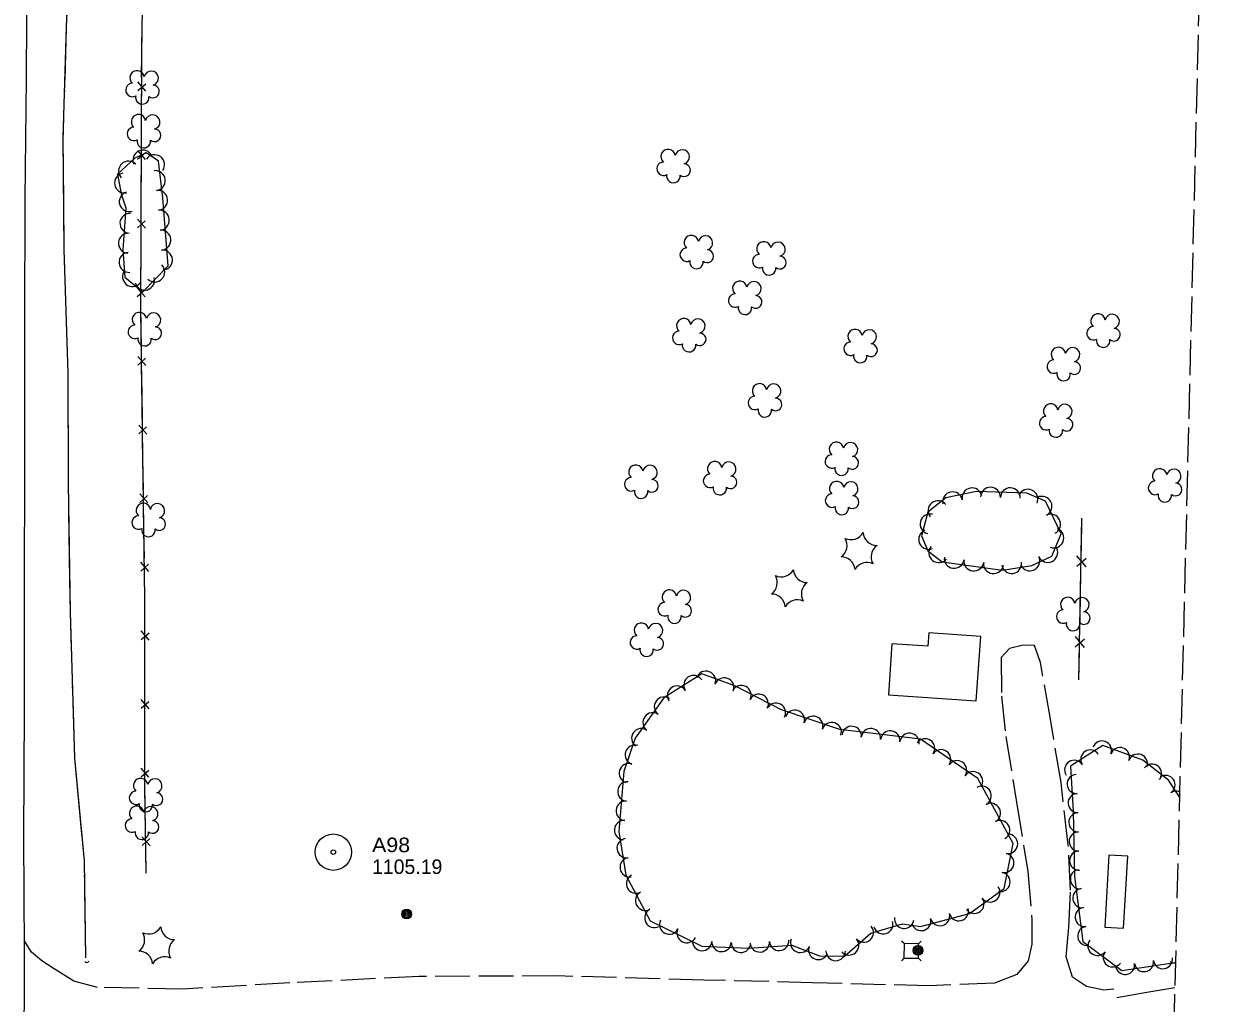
# Model space of a CAD drawing. Extents: x 296583 to 298831, y 44522 to 45957.
# Drawn here: x 297700.4 to 298192.3, y 45106.2 to 45510.3 of the extents above; entities that cross this region are included whole.
import ezdxf

# ---------------------------------------------------------------- set-up
doc = ezdxf.new("R2010")
doc.units = 0
doc.header["$LTSCALE"] = 2.4
doc.linetypes.add('LONG_DASHED', pattern=[7.5, 6, -1.5])
for name, color, linetype, lineweight in [('11', 7, 'Continuous', 25), ('12', 7, 'Continuous', 25), ('14', 7, 'Continuous', 13), ('15', 7, 'Continuous', 13), ('17', 7, 'LONG_DASHED', 13), ('18', 7, 'Continuous', 13), ('19', 7, 'Continuous', 13), ('21', 7, 'Continuous', 25), ('4', 7, 'Continuous', 13), ('6', 7, 'Continuous', 13)]:
    doc.layers.add(name, color=color, linetype=linetype, lineweight=lineweight)

msp = doc.modelspace()

# ---------------------------------------------------------------- linework, layer by layer
at = {"layer": '11'}
msp.add_lwpolyline([(297700.604, 45078.854), (297700.618, 45127.759), (297700.405, 45174.635), (297700.7, 45227.338), (297700.641, 45277.618), (297700.756, 45327.982), (297700.817, 45386.673), (297700.954, 45438.105), (297701.512, 45487.567), (297701.749, 45536.979), (297702.068, 45585.788), (297702.731, 45637.819), (297704.078, 45687.047), (297705.432, 45724.307), (297707.239, 45766.902), (297708.944, 45803.473), (297710.461, 45829.675)], dxfattribs=at)
at = {"layer": '12'}
for points in [[(298093.641, 45230.913), (298095.475, 45257.543), (298073.997, 45259.022), (298073.613, 45253.456), (298058.846, 45254.473), (298057.396, 45233.409)], [(298154.497, 45137.077), (298156.22, 45166.826), (298148.396, 45167.279), (298146.673, 45137.53)]]:
    msp.add_lwpolyline(points, close=True, dxfattribs=at)
at = {"layer": '14'}
for centre, radius in [((297858.511, 45142.941), 2.018), ((297858.498, 45142.938), 1.518), ((297858.538, 45142.944), 1.008), ((297858.528, 45142.948), 0.502), ((298069.604, 45127.957), 2.018), ((298069.591, 45127.954), 1.518), ((298069.631, 45127.96), 1.008), ((298069.621, 45127.964), 0.502)]:
    msp.add_circle(centre, radius, dxfattribs=at)
at = {"layer": '15'}
for p, q in [((297749.101, 45499.627), (297749.256, 45509.749)), ((297747.498, 45482.782), (297750.732, 45485.614)), ((297750.791, 45482.598), (297747.511, 45486.388)), ((297748.984, 45471.301), (297749.019, 45481.425)), ((297748.944, 45459.791), (297748.984, 45471.301)), ((297747.4, 45454.456), (297750.634, 45457.288)), ((297750.693, 45454.272), (297747.413, 45458.063)), ((297748.885, 45442.975), (297748.921, 45453.099)), ((297748.846, 45431.465), (297748.885, 45442.975)), ((297747.302, 45426.131), (297750.536, 45428.962)), ((297750.594, 45425.947), (297747.314, 45429.737)), ((297748.787, 45414.65), (297748.822, 45424.773)), ((297748.747, 45403.14), (297748.787, 45414.65)), ((297747.204, 45397.805), (297750.438, 45400.637)), ((297750.496, 45397.621), (297747.216, 45401.411)), ((297748.957, 45374.816), (297748.792, 45386.325)), ((297750.804, 45369.329), (297747.457, 45373.061)), ((297747.508, 45369.455), (297750.691, 45372.343)), ((297749.198, 45358.002), (297749.053, 45368.124)), ((297749.363, 45346.493), (297749.198, 45358.002)), ((297751.21, 45341.006), (297747.863, 45344.738)), ((297747.914, 45341.132), (297751.097, 45344.02)), ((297749.604, 45329.679), (297749.459, 45339.801)), ((297749.769, 45318.17), (297749.604, 45329.679)), ((297751.616, 45312.683), (297748.269, 45316.415)), ((297748.321, 45312.809), (297751.504, 45315.697)), ((297750.01, 45301.356), (297749.865, 45311.479)), ((298136.056, 45239.621), (298137.275, 45306.365)), ((298137.027, 45292.804), (298137.275, 45306.365)), ((297750.175, 45289.847), (297750.01, 45301.356)), ((297752.022, 45284.36), (297748.675, 45288.092)), ((298135.116, 45286.546), (298138.975, 45289.826)), ((298138.992, 45286.271), (298135.193, 45290.795)), ((297748.727, 45284.486), (297751.91, 45287.375)), ((297750.416, 45273.033), (297750.271, 45283.156)), ((298136.666, 45272.993), (298136.883, 45284.92)), ((298136.418, 45259.432), (298136.666, 45272.993)), ((297748.869, 45256.185), (297752.097, 45259.024)), ((297752.162, 45256.008), (297748.874, 45259.792)), ((297750.379, 45244.707), (297750.393, 45254.831)), ((298134.506, 45253.174), (298138.366, 45256.454)), ((298138.382, 45252.899), (298134.584, 45257.423)), ((298136.056, 45239.621), (298136.274, 45251.548)), ((297750.363, 45233.197), (297750.379, 45244.707)), ((297748.831, 45227.859), (297752.059, 45230.698)), ((297752.124, 45227.682), (297748.836, 45231.466)), ((297750.341, 45216.382), (297750.354, 45226.505)), ((297750.325, 45204.871), (297750.341, 45216.382)), ((297748.793, 45199.534), (297752.021, 45202.372)), ((297752.086, 45199.356), (297748.798, 45203.14)), ((297750.648, 45176.549), (297750.438, 45188.057)), ((297752.516, 45171.069), (297749.154, 45174.788)), ((297749.22, 45171.182), (297752.392, 45174.083)), ((297750.954, 45159.736), (297750.77, 45169.858))]:
    msp.add_line(p, q, dxfattribs=at)
for points in [[(297750.954, 45159.736), (297750.312, 45194.971), (297750.417, 45272.978), (297748.709, 45392.083), (297749.076, 45497.953), (297750.665, 45602.374), (297754.315, 45709.699), (297757.299, 45776.061), (297759.438, 45839.359)], [(297749.042, 45488.117), (297749.076, 45497.953), (297749.101, 45499.627)], [(297748.792, 45386.325), (297748.709, 45392.083), (297748.724, 45396.448)], [(297750.402, 45261.523), (297750.417, 45272.978), (297750.416, 45273.033)], [(297750.438, 45188.057), (297750.312, 45194.971), (297750.316, 45198.179)]]:
    msp.add_lwpolyline(points, dxfattribs=at)
msp.add_arc((297726.382, 45124.066), 1.068, 217.51639, 323.75596, dxfattribs=at)
at = {"layer": '17'}
for points in [[(298150.422, 45111.928), (298146.293, 45111.523), (298139.171, 45113.083), (298133.366, 45116.913), (298130.79, 45125.314), (298131.91, 45137.522), (298132.54, 45152.831), (298131.641, 45171.346), (298128.674, 45197.228), (298124.272, 45223.339), (298120.181, 45246.762), (298117.621, 45253.745), (298113.041, 45253.963), (298107.373, 45252.469), (298103.951, 45248.761), (298104.086, 45232.906), (298105.855, 45216.199), (298110.309, 45189.111), (298114.899, 45160.471), (298116.651, 45140.372), (298116.652, 45130.449), (298115.051, 45123.584), (298110.394, 45117.953), (298101.195, 45114.428), (298074.198, 45113.28), (298026.037, 45114.598), (297981.096, 45115.677), (297920.614, 45117.389), (297863.611, 45117.162), (297810.275, 45114.518), (297766.019, 45111.98), (297730.888, 45112.634), (297721.051, 45115.297), (297712.957, 45120.288), (297707.796, 45123.568), (297703.637, 45127.194), (297700.599, 45132.01)], [(298151.682, 45108.52), (298164.075, 45110.74), (298175.618, 45112.686)]]:
    msp.add_lwpolyline(points, dxfattribs=at)
at = {"layer": '18'}
for points in [[(297739.149, 45448.318), (297740.617, 45440.211), (297742.502, 45434.351), (297741.26, 45417.106), (297742.138, 45405.773), (297749.583, 45399.778), (297759.991, 45410.477), (297757.731, 45438.5), (297755.941, 45453.686), (297751.042, 45457.155), (297746.201, 45454.912)], [(298104.537, 45284.828), (298116.614, 45286.711), (298124.9, 45290.602), (298128.707, 45299.852), (298122.181, 45313.301), (298114.549, 45316.691), (298093.801, 45317.294), (298081.064, 45314.666), (298073.6, 45308.805), (298071.019, 45298.976), (298073.7, 45292.847), (298079.536, 45288.224)], [(298090.837, 45143.154), (298105.215, 45153.446), (298108.897, 45172.021), (298094.318, 45198.905), (298070.605, 45215.121), (298037.286, 45219.121), (298013.251, 45227.181), (297993.956, 45237.063), (297980.298, 45242.069), (297964.705, 45232.099), (297952.75, 45215.512), (297948.188, 45201.706), (297946.097, 45176.958), (297948.958, 45158.947), (297959.036, 45140.097), (297980.271, 45129.706), (297999.867, 45128.812), (298017.508, 45130.154), (298028.902, 45125.679), (298039.226, 45125.563), (298050.134, 45135.038), (298063.173, 45138.949), (298070.629, 45137.835)]]:
    msp.add_lwpolyline(points, close=True, dxfattribs=at)
msp.add_lwpolyline([(298177.543, 45191.331), (298172.95, 45198.187), (298162.451, 45206.457), (298145.877, 45212.524), (298132.607, 45203.963), (298133.619, 45185.431), (298134.192, 45158.472), (298137.653, 45131.66), (298153.812, 45119.639), (298175.82, 45122.997), (298175.873, 45123.078)], dxfattribs=at)
for centre, radius, start, end in [((297747.165, 45488.034), 2.974, 7.98733, 229.22121), ((297753.017, 45487.878), 2.975, 285.63814, 168.61141), ((297745.269, 45483.006), 2.777, 90.95822, 298.73121), ((297753.74, 45482.404), 2.611, 230.34337, 88.27598), ((297749.322, 45479.975), 2.783, 167.63523, 8.64628), ((297747.756, 45469.939), 2.974, 7.98733, 229.22121), ((297753.608, 45469.783), 2.975, 285.63814, 168.61141), ((297745.86, 45464.911), 2.777, 90.95822, 298.73121), ((297754.331, 45464.309), 2.611, 230.34337, 88.27598), ((297749.913, 45461.88), 2.783, 167.63523, 8.64628), ((297749.571, 45454.095), 4.123, 24.86756, 204.85223), ((297754.385, 45452.144), 4.123, 324.70521, 144.68989), ((297966.431, 45455.552), 2.974, 7.98733, 229.22121), ((297972.283, 45455.396), 2.975, 285.63814, 168.61141), ((297743.634, 45449.557), 4.123, 43.08537, 223.07004), ((297754.719, 45445.62), 4.123, 276.73019, 96.71487), ((297964.535, 45450.524), 2.777, 90.95822, 298.73121), ((297973.006, 45449.922), 2.611, 230.34337, 88.27598), ((297742.007, 45444.645), 4.123, 100.27146, 280.25613), ((297968.588, 45447.493), 2.783, 167.63523, 8.64628), ((297743.936, 45436.94), 4.123, 107.83921, 287.82389), ((297755.646, 45437.507), 4.123, 274.61847, 94.60315), ((297744.208, 45427.991), 4.123, 85.88828, 265.87296), ((297756.309, 45429.288), 4.123, 274.61847, 94.60315), ((297756.972, 45421.069), 4.123, 274.61847, 94.60315), ((297743.615, 45419.767), 4.123, 85.88828, 265.87296), ((297975.992, 45420.052), 2.974, 7.98733, 229.22121), ((297981.844, 45419.896), 2.975, 285.63814, 168.61141), ((298005.955, 45417.43), 2.974, 7.98733, 229.22121), ((298011.807, 45417.274), 2.975, 285.63814, 168.61141), ((297743.831, 45411.866), 4.123, 94.43768, 274.42236), ((297757.634, 45412.85), 4.123, 274.61847, 94.60315), ((297974.096, 45415.024), 2.777, 90.95822, 298.73121), ((297982.567, 45414.422), 2.611, 230.34337, 88.27598), ((297754.475, 45407.902), 4.123, 225.79754, 45.78222), ((297978.149, 45411.993), 2.783, 167.63523, 8.64628), ((298004.059, 45412.402), 2.777, 90.95822, 298.73121), ((298012.53, 45411.8), 2.611, 230.34337, 88.27598), ((297745.284, 45406.01), 4.123, 141.16531, 321.14999), ((297750.309, 45404.581), 4.123, 195.79754, 15.78222), ((298008.112, 45409.371), 2.783, 167.63523, 8.64628), ((297995.994, 45401.167), 2.974, 7.98733, 229.22121), ((298001.846, 45401.011), 2.975, 285.63814, 168.61141), ((297994.098, 45396.139), 2.777, 90.95822, 298.73121), ((298002.569, 45395.537), 2.611, 230.34337, 88.27598), ((297748.122, 45388.246), 2.974, 7.98733, 229.22121), ((297753.974, 45388.09), 2.975, 285.63814, 168.61141), ((297998.151, 45393.108), 2.783, 167.63523, 8.64628), ((297746.226, 45383.218), 2.777, 90.95822, 298.73121), ((297972.886, 45385.751), 2.974, 7.98733, 229.22121), ((297978.738, 45385.595), 2.975, 285.63814, 168.61141), ((298143.914, 45387.655), 2.974, 7.98733, 229.22121), ((298149.766, 45387.499), 2.975, 285.63814, 168.61141), ((297754.697, 45382.616), 2.611, 230.34337, 88.27598), ((297970.99, 45380.723), 2.777, 90.95822, 298.73121), ((297979.461, 45380.121), 2.611, 230.34337, 88.27598), ((298043.621, 45381.257), 2.974, 7.98733, 229.22121), ((298049.473, 45381.101), 2.975, 285.63814, 168.61141), ((298142.018, 45382.627), 2.777, 90.95822, 298.73121), ((298150.489, 45382.025), 2.611, 230.34337, 88.27598), ((297750.279, 45380.187), 2.783, 167.63523, 8.64628), ((297975.043, 45377.692), 2.783, 167.63523, 8.64628), ((298041.725, 45376.229), 2.777, 90.95822, 298.73121), ((298050.196, 45375.627), 2.611, 230.34337, 88.27598), ((298127.567, 45373.881), 2.974, 7.98733, 229.22121), ((298133.419, 45373.725), 2.975, 285.63814, 168.61141), ((298146.071, 45379.596), 2.783, 167.63523, 8.64628), ((298045.778, 45373.198), 2.783, 167.63523, 8.64628), ((298125.671, 45368.853), 2.777, 90.95822, 298.73121), ((298129.724, 45365.822), 2.783, 167.63523, 8.64628), ((298134.142, 45368.251), 2.611, 230.34337, 88.27598), ((298004.148, 45358.889), 2.974, 7.98733, 229.22121), ((298010, 45358.733), 2.975, 285.63814, 168.61141), ((298002.252, 45353.861), 2.777, 90.95822, 298.73121), ((298006.305, 45350.83), 2.783, 167.63523, 8.64628), ((298010.723, 45353.259), 2.611, 230.34337, 88.27598), ((298124.369, 45350.519), 2.974, 7.98733, 229.22121), ((298130.221, 45350.363), 2.975, 285.63814, 168.61141), ((298122.473, 45345.491), 2.777, 90.95822, 298.73121), ((298130.944, 45344.889), 2.611, 230.34337, 88.27598), ((298126.526, 45342.46), 2.783, 167.63523, 8.64628), ((298035.892, 45334.744), 2.974, 7.98733, 229.22121), ((298041.744, 45334.588), 2.975, 285.63814, 168.61141), ((298033.996, 45329.716), 2.777, 90.95822, 298.73121), ((298042.467, 45329.114), 2.611, 230.34337, 88.27598), ((297953.107, 45325.312), 2.974, 7.98733, 229.22121), ((297958.959, 45325.156), 2.975, 285.63814, 168.61141), ((297985.624, 45326.736), 2.974, 7.98733, 229.22121), ((297991.476, 45326.58), 2.975, 285.63814, 168.61141), ((298038.049, 45326.685), 2.783, 167.63523, 8.64628), ((298169.358, 45323.772), 2.974, 7.98733, 229.22121), ((297951.211, 45320.284), 2.777, 90.95822, 298.73121), ((297959.682, 45319.682), 2.611, 230.34337, 88.27598), ((297983.728, 45321.708), 2.777, 90.95822, 298.73121), ((297992.199, 45321.106), 2.611, 230.34337, 88.27598), ((298175.21, 45323.616), 2.975, 285.63814, 168.61141), ((297955.264, 45317.253), 2.783, 167.63523, 8.64628), ((297987.781, 45318.677), 2.783, 167.63523, 8.64628), ((298035.999, 45318.553), 2.974, 7.98733, 229.22121), ((298041.851, 45318.397), 2.975, 285.63814, 168.61141), ((298083.87, 45313.056), 4.097, 11.66579, 191.65047), ((298091.894, 45314.711), 4.097, 11.66579, 191.65047), ((298099.538, 45314.982), 4.097, 358.34294, 178.32762), ((298107.727, 45314.744), 4.097, 358.34294, 178.32762), ((298114.985, 45314.151), 4.097, 336.05771, 156.04239), ((298167.462, 45318.744), 2.777, 90.95822, 298.73121), ((298175.933, 45318.142), 2.611, 230.34337, 88.27598), ((297749.72, 45309.511), 2.974, 7.98733, 229.22121), ((297755.572, 45309.355), 2.975, 285.63814, 168.61141), ((298034.103, 45313.525), 2.777, 90.95822, 298.73121), ((298042.574, 45312.923), 2.611, 230.34337, 88.27598), ((298077.851, 45309.417), 4.097, 38.14793, 218.13261), ((298120.807, 45311.222), 4.097, 295.8922, 115.87688), ((298171.515, 45315.713), 2.783, 167.63523, 8.64628), ((297747.824, 45304.483), 2.777, 90.95822, 298.73121), ((298038.156, 45310.494), 2.783, 167.63523, 8.64628), ((298074.538, 45303.936), 4.097, 75.29452, 255.27919), ((298124.383, 45303.851), 4.097, 295.8922, 115.87688), ((297756.295, 45303.881), 2.611, 230.34337, 88.27598), ((297751.877, 45301.452), 2.783, 167.63523, 8.64628), ((298034.564, 45295.07), 5.725, 304.77499, 30.5399), ((298041.934, 45303.158), 5.725, 244.775, 330.53991), ((298052.621, 45300.821), 5.725, 184.775, 270.53991), ((298073.986, 45297.544), 4.097, 113.63361, 293.61828), ((298125.694, 45298.165), 4.097, 247.63719, 67.62186), ((298055.941, 45290.393), 5.725, 124.775, 210.53991), ((298078.17, 45292.042), 4.097, 141.62308, 321.60776), ((298123.178, 45292.162), 4.097, 205.16181, 25.14649), ((298037.882, 45284.644), 5.725, 4.77499, 90.5399), ((298048.571, 45282.306), 5.725, 64.77499, 150.5399), ((298084.532, 45289.709), 4.097, 172.27226, 352.25694), ((298092.65, 45288.607), 4.097, 172.27226, 352.25694), ((298100.767, 45287.504), 4.097, 172.27226, 352.25694), ((298108.254, 45287.578), 4.097, 188.86965, 8.85433), ((298115.762, 45288.68), 4.097, 205.16181, 25.14649), ((298005.773, 45279.698), 5.725, 304.77499, 30.5399), ((298013.143, 45287.786), 5.725, 244.775, 330.53991), ((298023.83, 45285.449), 5.725, 184.775, 270.53991), ((298027.15, 45275.021), 5.725, 124.775, 210.53991), ((297966.9, 45273.743), 2.974, 7.98733, 229.22121), ((297972.752, 45273.587), 2.975, 285.63814, 168.61141), ((298009.091, 45269.272), 5.725, 4.77499, 90.5399), ((298019.78, 45266.934), 5.725, 64.77499, 150.5399), ((298131.439, 45270.711), 2.974, 7.98733, 229.22121), ((298137.291, 45270.555), 2.975, 285.63814, 168.61141), ((297965.004, 45268.715), 2.777, 90.95822, 298.73121), ((297973.475, 45268.113), 2.611, 230.34337, 88.27598), ((298129.543, 45265.683), 2.777, 90.95822, 298.73121), ((297955.389, 45260.066), 2.974, 7.98733, 229.22121), ((297961.241, 45259.91), 2.975, 285.63814, 168.61141), ((297969.057, 45265.684), 2.783, 167.63523, 8.64628), ((298133.596, 45262.652), 2.783, 167.63523, 8.64628), ((298138.014, 45265.081), 2.611, 230.34337, 88.27598), ((297953.493, 45255.038), 2.777, 90.95822, 298.73121), ((297961.964, 45254.436), 2.611, 230.34337, 88.27598), ((297957.546, 45252.007), 2.783, 167.63523, 8.64628), ((297982.05, 45239.192), 4.01, 339.87851, 159.86319), ((297976.893, 45237.401), 4.01, 32.60208, 212.58676), ((297989.578, 45236.432), 4.01, 339.87851, 159.86319), ((297970.138, 45233.082), 4.01, 32.60208, 212.58676), ((297996.671, 45233.315), 4.01, 332.88825, 152.87293), ((298003.807, 45229.66), 4.01, 332.88825, 152.87293), ((297964.705, 45228.51), 4.01, 54.22567, 234.21034), ((298010.944, 45226.005), 4.01, 332.88825, 152.87293), ((297960.017, 45222.005), 4.01, 54.22567, 234.21034), ((298018.747, 45223.124), 4.01, 341.46908, 161.45376), ((298026.349, 45220.575), 4.01, 341.46908, 161.45376), ((297955.329, 45215.501), 4.01, 54.22567, 234.21034), ((298033.952, 45218.026), 4.01, 341.46908, 161.45376), ((298042.204, 45216.417), 4.01, 353.16197, 173.14665), ((298050.165, 45215.461), 4.01, 353.16197, 173.14665), ((298058.126, 45214.506), 4.01, 353.16197, 173.14665), ((298066.087, 45213.55), 4.01, 353.16197, 173.14665), ((298072.49, 45211.289), 4.01, 325.64161, 145.62629), ((298145.559, 45210.44), 3.948, 339.90224, 159.88692), ((297952.697, 45208.663), 4.01, 71.72224, 251.70692), ((298079.109, 45206.763), 4.01, 325.64161, 145.62629), ((298140.714, 45206.734), 3.948, 32.83532, 212.82), ((298152.972, 45207.727), 3.948, 339.90224, 159.88692), ((298160.385, 45205.013), 3.948, 339.90224, 159.88692), ((297950.181, 45201.05), 4.01, 71.72224, 251.70692), ((298085.728, 45202.237), 4.01, 325.64161, 145.62629), ((298134.081, 45202.455), 3.948, 32.83532, 212.82), ((298166.24, 45200.843), 3.948, 321.78037, 141.76504), ((297748.625, 45195.957), 2.974, 7.98733, 229.22121), ((298092.346, 45197.711), 4.01, 325.64161, 145.62629), ((298135.078, 45196.613), 3.948, 93.13338, 273.11806), ((298171.779, 45196.223), 3.948, 303.82663, 123.81131), ((297754.477, 45195.801), 2.975, 285.63814, 168.61141), ((297949.604, 45193.542), 4.01, 85.17812, 265.16279), ((298095.841, 45191.695), 4.01, 298.47832, 118.463), ((297746.729, 45190.929), 2.777, 90.95822, 298.73121), ((297755.2, 45190.327), 2.611, 230.34337, 88.27598), ((297948.929, 45185.552), 4.01, 85.17812, 265.16279), ((298135.508, 45188.731), 3.948, 93.13338, 273.11806), ((298176.172, 45189.665), 3.948, 68.9124, 123.81131), ((297746.956, 45184.494), 2.974, 7.98733, 229.22121), ((297750.782, 45187.898), 2.783, 167.63523, 8.64628), ((297752.808, 45184.338), 2.975, 285.63814, 168.61141), ((298099.663, 45184.646), 4.01, 298.47832, 118.463), ((298135.785, 45180.774), 3.948, 91.22527, 271.20995), ((297745.06, 45179.466), 2.777, 90.95822, 298.73121), ((297753.531, 45178.864), 2.611, 230.34337, 88.27598), ((297948.254, 45177.563), 4.01, 85.17812, 265.16279), ((298103.486, 45177.598), 4.01, 298.47832, 118.463), ((297749.113, 45176.435), 2.783, 167.63523, 8.64628), ((298106.734, 45171.903), 4.01, 258.79564, 78.78032), ((298135.952, 45172.881), 3.948, 91.22527, 271.20995), ((297949.304, 45170.143), 4.01, 99.03353, 279.01821), ((297950.562, 45162.224), 4.01, 99.03353, 279.01821), ((298105.175, 45164.038), 4.01, 258.79564, 78.78032), ((298136.12, 45164.989), 3.948, 91.22527, 271.20995), ((298103.616, 45156.173), 4.01, 258.79564, 78.78032), ((298136.423, 45157.328), 3.948, 97.36296, 277.34763), ((297953.182, 45155.498), 4.01, 118.13849, 298.12317), ((297956.962, 45148.427), 4.01, 118.13849, 298.12317), ((298099.396, 45151.861), 4.01, 215.60335, 35.58803), ((298137.433, 45149.499), 3.948, 97.36296, 277.34763), ((297960.743, 45141.356), 4.01, 118.13849, 298.12317), ((298086.426, 45144.163), 4.01, 194.75416, 14.73883), ((298092.876, 45147.194), 4.01, 215.60335, 35.58803), ((298138.444, 45141.67), 3.948, 97.36296, 277.34763), ((297966.886, 45138.592), 4.01, 153.9336, 333.91828), ((298055.246, 45138.762), 4.01, 196.70408, 16.68876), ((298063.851, 45140.97), 4.01, 171.50997, 351.49464), ((298070.918, 45140.081), 4.01, 194.75416, 14.73883), ((298078.672, 45142.122), 4.01, 194.75416, 14.73883), ((297744.568, 45132.335), 5.725, 304.77499, 30.5399), ((297751.938, 45140.423), 5.725, 244.775, 330.53991), ((297762.625, 45138.086), 5.725, 184.775, 270.53991), ((297974.088, 45135.068), 4.01, 153.9336, 333.91828), ((298047.209, 45135.277), 4.01, 220.98618, 40.97085), ((298139.455, 45133.841), 3.948, 97.36296, 277.34763), ((297765.945, 45127.658), 5.725, 124.775, 210.53991), ((297980.475, 45131.797), 4.01, 177.39555, 357.38023), ((297988.485, 45131.432), 4.01, 177.39555, 357.38023), ((297996.494, 45131.067), 4.01, 177.39555, 357.38023), ((298004.241, 45131.249), 4.01, 184.35793, 4.34261), ((298012.236, 45131.858), 4.01, 184.35793, 4.34261), ((298020.966, 45131.051), 4.01, 158.56521, 338.54989), ((298041.156, 45130.019), 4.01, 220.98618, 40.97085), ((298143.67, 45129.759), 3.948, 143.36137, 323.34605), ((297747.886, 45121.909), 5.725, 4.77499, 90.5399), ((297758.575, 45119.571), 5.725, 64.77499, 150.5399), ((298028.429, 45128.119), 4.01, 158.56521, 338.54989), ((298035.611, 45127.702), 4.01, 179.36392, 359.34859), ((298150.004, 45125.047), 3.948, 143.36137, 323.34605), ((298155.092, 45121.924), 3.948, 188.68299, 8.66767), ((298162.896, 45123.115), 3.948, 188.68299, 8.66767), ((298170.7, 45124.306), 3.948, 188.68299, 8.66767), ((298175.742, 45126.664), 3.948, 236.93552, 271.76682)]:
    msp.add_arc(centre, radius, start, end, dxfattribs=at)
at = {"layer": '19'}
for p, q in [((297717.231, 45481.132), (297717.29, 45483.085)), ((297717.052, 45475.274), (297717.112, 45477.227)), ((297716.873, 45469.415), (297716.933, 45471.368)), ((297717.522, 45402.995), (297717.461, 45404.948)), ((297717.706, 45397.136), (297717.645, 45399.089)), ((297717.89, 45391.277), (297717.829, 45393.23)), ((297718.832, 45330.718), (297718.707, 45359.05)), ((297718.858, 45324.856), (297718.85, 45326.81)), ((297718.984, 45313.134), (297718.956, 45315.087)), ((297719.443, 45280.898), (297719.04, 45309.226)), ((297720.26, 45246.715), (297720.201, 45248.668)), ((297720.436, 45240.856), (297720.377, 45242.809)), ((297720.612, 45234.997), (297720.554, 45236.95)), ((297724.495, 45174.581), (297721.864, 45202.789)), ((297725.039, 45168.745), (297724.858, 45170.69)), ((297725.433, 45162.9), (297725.401, 45164.854)), ((297725.529, 45157.039), (297725.497, 45158.993)), ((297726.055, 45124.806), (297725.593, 45153.132))]:
    msp.add_line(p, q, dxfattribs=at)
for points in [[(297726.055, 45124.806), (297725.401, 45164.864), (297721.448, 45207.244), (297719.634, 45267.49), (297718.877, 45320.671), (297718.675, 45366.263), (297717.075, 45417.239), (297716.686, 45463.269), (297718.083, 45509.09), (297719.87, 45556.428), (297719.531, 45602.258), (297717.786, 45649.534), (297721.321, 45707.634), (297724.469, 45758.303), (297729.206, 45810.224), (297731.165, 45827.332)], [(297717.409, 45486.991), (297718.083, 45509.09), (297718.318, 45515.307)], [(297716.906, 45437.18), (297716.686, 45463.269), (297716.754, 45465.509)], [(297717.338, 45408.853), (297717.075, 45417.239), (297716.906, 45437.18)], [(297718.707, 45359.05), (297718.675, 45366.263), (297718.012, 45387.371)], [(297718.901, 45318.995), (297718.877, 45320.671), (297718.876, 45320.948)], [(297720.083, 45252.574), (297719.634, 45267.49), (297719.443, 45280.898)], [(297721.864, 45202.789), (297721.448, 45207.244), (297720.73, 45231.091)]]:
    msp.add_lwpolyline(points, dxfattribs=at)
at = {"layer": '21'}
for p, q in [((298063.847, 45130.738), (298062.795, 45131.807)), ((298070.916, 45131.745), (298069.846, 45130.693)), ((298063.801, 45124.738), (298062.732, 45123.687)), ((298070.853, 45123.624), (298069.8, 45124.692))]:
    msp.add_line(p, q, dxfattribs=at)
msp.add_lwpolyline([(298069.8, 45124.692), (298069.846, 45130.693), (298063.847, 45130.738), (298063.801, 45124.738)], close=True, dxfattribs=at)
at = {"layer": '4', "linetype": 'LONG_DASHED'}
msp.add_line((298192.285, 45793.642), (298163.649, 44623.641), dxfattribs=at)
at = {"layer": '6'}
for radius in [7.5, 0.96]:
    msp.add_circle((297828.191, 45168.473), radius, dxfattribs=at)

# ---------------------------------------------------------------- texts
at = {"layer": '6', "width": 1.1}
msp.add_text('A98', height=6, dxfattribs=at).set_placement((297844.191, 45168.473))
at = {"layer": '6'}
msp.add_text('1105.19', height=6, dxfattribs=at).set_placement((297844.191, 45159.473))

doc.saveas('drawing.dxf')
